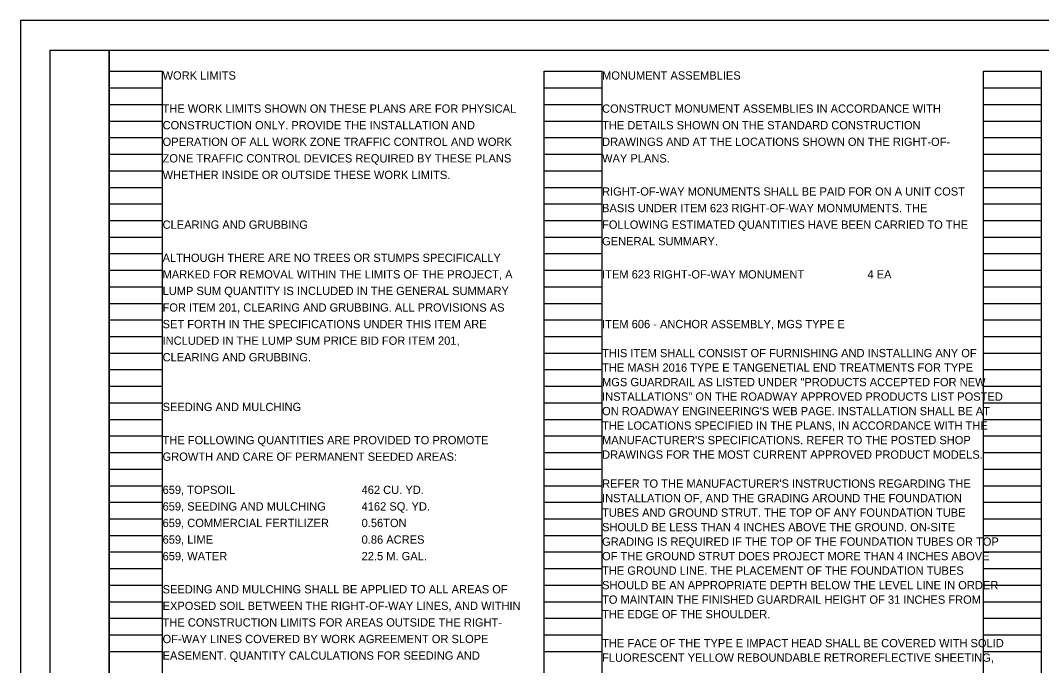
# Model space of a CAD drawing. Extents: x 0 to 34, y 0 to 22.
# Drawn here: x 0 to 17.24, y 11.1 to 22 of the extents above; entities that cross this region are included whole.
import ezdxf

# ---------------------------------------------------------------- set-up
doc = ezdxf.new("R2010")
doc.units = 0
for name, color, linetype in [('Default', 7, 'Continuous'), ('SH_Border', 7, 'Continuous'), ('SH_Cut_Line', 7, 'Continuous'), ('SH_Data', 7, 'Continuous'), ('SH_Text', 7, 'Continuous')]:
    doc.layers.add(name, color=color, linetype=linetype)

msp = doc.modelspace()

# ---------------------------------------------------------------- linework, layer by layer
at = {"layer": 'SH_Border'}
for points in [[(0.5, 21.5), (1.5, 21.5), (1.5, 0.5), (0.5, 0.5)], [(1.5, 21.5), (33.5, 21.5), (33.5, 0.5), (1.5, 0.5)]]:
    msp.add_lwpolyline(points, close=True, dxfattribs=at)
at = {"layer": 'SH_Cut_Line'}
msp.add_lwpolyline([(0, 0), (34, 0), (34, 22), (0, 22)], close=True, dxfattribs=at)
at = {"layer": 'SH_Data'}
for p, q in [((1.5, 0.98), (1.5, 21.14)), ((1.5, 21.14), (2.4, 21.14)), ((2.4, 0.98), (2.4, 21.14)), ((8.84, 0.98), (8.84, 21.14)), ((8.84, 21.14), (9.82, 21.14)), ((9.82, 0.98), (9.82, 21.14)), ((16.26, 0.98), (16.26, 21.14)), ((16.26, 21.14), (17.24, 21.14)), ((17.24, 0.98), (17.24, 21.14)), ((1.5, 20.86), (2.4, 20.86)), ((8.84, 20.86), (9.82, 20.86)), ((16.26, 20.86), (17.24, 20.86)), ((1.5, 20.58), (2.4, 20.58)), ((8.84, 20.58), (9.82, 20.58)), ((16.26, 20.58), (17.24, 20.58)), ((1.5, 20.3), (2.4, 20.3)), ((8.84, 20.3), (9.82, 20.3)), ((16.26, 20.3), (17.24, 20.3)), ((1.5, 20.02), (2.4, 20.02)), ((8.84, 20.02), (9.82, 20.02)), ((16.26, 20.02), (17.24, 20.02)), ((1.5, 19.74), (2.4, 19.74)), ((8.84, 19.74), (9.82, 19.74)), ((16.26, 19.74), (17.24, 19.74)), ((1.5, 19.46), (2.4, 19.46)), ((8.84, 19.46), (9.82, 19.46)), ((16.26, 19.46), (17.24, 19.46)), ((1.5, 19.18), (2.4, 19.18)), ((8.84, 19.18), (9.82, 19.18)), ((16.26, 19.18), (17.24, 19.18)), ((1.5, 18.9), (2.4, 18.9)), ((8.84, 18.9), (9.82, 18.9)), ((16.26, 18.9), (17.24, 18.9)), ((1.5, 18.62), (2.4, 18.62)), ((8.84, 18.62), (9.82, 18.62)), ((16.26, 18.62), (17.24, 18.62)), ((1.5, 18.34), (2.4, 18.34)), ((8.84, 18.34), (9.82, 18.34)), ((16.26, 18.34), (17.24, 18.34)), ((1.5, 18.06), (2.4, 18.06)), ((8.84, 18.06), (9.82, 18.06)), ((16.26, 18.06), (17.24, 18.06)), ((1.5, 17.78), (2.4, 17.78)), ((8.84, 17.78), (9.82, 17.78)), ((16.26, 17.78), (17.24, 17.78)), ((1.5, 17.5), (2.4, 17.5)), ((8.84, 17.5), (9.82, 17.5)), ((16.26, 17.5), (17.24, 17.5)), ((1.5, 17.22), (2.4, 17.22)), ((8.84, 17.22), (9.82, 17.22)), ((16.26, 17.22), (17.24, 17.22)), ((1.5, 16.94), (2.4, 16.94)), ((8.84, 16.94), (9.82, 16.94)), ((16.26, 16.94), (17.24, 16.94)), ((1.5, 16.66), (2.4, 16.66)), ((8.84, 16.66), (9.82, 16.66)), ((16.26, 16.66), (17.24, 16.66)), ((1.5, 16.38), (2.4, 16.38)), ((8.84, 16.38), (9.82, 16.38)), ((16.26, 16.38), (17.24, 16.38)), ((1.5, 16.1), (2.4, 16.1)), ((8.84, 16.1), (9.82, 16.1)), ((16.26, 16.1), (17.24, 16.1)), ((1.5, 15.82), (2.4, 15.82)), ((8.84, 15.82), (9.82, 15.82)), ((16.26, 15.82), (17.24, 15.82)), ((1.5, 15.54), (2.4, 15.54)), ((8.84, 15.54), (9.82, 15.54)), ((16.26, 15.54), (17.24, 15.54)), ((1.5, 15.26), (2.4, 15.26)), ((8.84, 15.26), (9.82, 15.26)), ((16.26, 15.26), (17.24, 15.26)), ((1.5, 14.98), (2.4, 14.98)), ((8.84, 14.98), (9.82, 14.98)), ((16.26, 14.98), (17.24, 14.98)), ((1.5, 14.7), (2.4, 14.7)), ((8.84, 14.7), (9.82, 14.7)), ((16.26, 14.7), (17.24, 14.7)), ((1.5, 14.42), (2.4, 14.42)), ((8.84, 14.42), (9.82, 14.42)), ((16.26, 14.42), (17.24, 14.42)), ((1.5, 14.14), (2.4, 14.14)), ((8.84, 14.14), (9.82, 14.14)), ((16.26, 14.14), (17.24, 14.14)), ((1.5, 13.86), (2.4, 13.86)), ((8.84, 13.86), (9.82, 13.86)), ((16.26, 13.86), (17.24, 13.86)), ((1.5, 13.58), (2.4, 13.58)), ((8.84, 13.58), (9.82, 13.58)), ((16.26, 13.58), (17.24, 13.58)), ((1.5, 13.3), (2.4, 13.3)), ((8.84, 13.3), (9.82, 13.3)), ((16.26, 13.3), (17.24, 13.3)), ((1.5, 13.02), (2.4, 13.02)), ((8.84, 13.02), (9.82, 13.02)), ((16.26, 13.02), (17.24, 13.02)), ((1.5, 12.74), (2.4, 12.74)), ((8.84, 12.74), (9.82, 12.74)), ((16.26, 12.74), (17.24, 12.74)), ((1.5, 12.46), (2.4, 12.46)), ((8.84, 12.46), (9.82, 12.46)), ((16.26, 12.46), (17.24, 12.46)), ((1.5, 12.18), (2.4, 12.18)), ((8.84, 12.18), (9.82, 12.18)), ((16.26, 12.18), (17.24, 12.18)), ((1.5, 11.9), (2.4, 11.9)), ((8.84, 11.9), (9.82, 11.9)), ((16.26, 11.9), (17.24, 11.9)), ((1.5, 11.62), (2.4, 11.62)), ((8.84, 11.62), (9.82, 11.62)), ((16.26, 11.62), (17.24, 11.62)), ((1.5, 11.34), (2.4, 11.34)), ((8.84, 11.34), (9.82, 11.34)), ((16.26, 11.34), (17.24, 11.34))]:
    msp.add_line(p, q, dxfattribs=at)

# ---------------------------------------------------------------- texts
at = {"layer": 'Default'}
for s, p in [('MONUMENT ASSEMBLIES', (9.82, 21)), ('CONSTRUCT MONUMENT ASSEMBLIES IN ACCORDANCE WITH', (9.82, 20.44)), ('THE DETAILS SHOWN ON THE STANDARD CONSTRUCTION', (9.82, 20.16)), ('DRAWINGS AND AT THE LOCATIONS SHOWN ON THE RIGHT-OF-', (9.82, 19.88)), ('WAY PLANS.', (9.82, 19.6)), ('RIGHT-OF-WAY MONUMENTS SHALL BE PAID FOR ON A UNIT COST ', (9.82, 19.04)), ('BASIS UNDER ITEM 623 RIGHT-OF-WAY MONMUMENTS. THE ', (9.82, 18.76)), ('FOLLOWING ESTIMATED QUANTITIES HAVE BEEN CARRIED TO THE ', (9.82, 18.48)), ('GENERAL SUMMARY.', (9.82, 18.2)), ('ITEM 623 RIGHT-OF-WAY MONUMENT', (9.82, 17.64)), ('4 EA', (14.3, 17.64))]:
    msp.add_text(s, height=0.14, dxfattribs=at).set_placement(p)
at = {"layer": 'SH_Text'}
for s, p in [('WORK LIMITS', (2.4, 21)), ('THE WORK LIMITS SHOWN ON THESE PLANS ARE FOR PHYSICAL', (2.4, 20.44)), ('CONSTRUCTION ONLY. PROVIDE THE INSTALLATION AND', (2.4, 20.16)), ('OPERATION OF ALL WORK ZONE TRAFFIC CONTROL AND WORK', (2.4, 19.88)), ('ZONE TRAFFIC CONTROL DEVICES REQUIRED BY THESE PLANS', (2.4, 19.6)), ('WHETHER INSIDE OR OUTSIDE THESE WORK LIMITS.', (2.4, 19.32)), ('CLEARING AND GRUBBING', (2.4, 18.48)), ('ALTHOUGH THERE ARE NO TREES OR STUMPS SPECIFICALLY', (2.4, 17.92)), ('MARKED FOR REMOVAL WITHIN THE LIMITS OF THE PROJECT, A', (2.4, 17.64)), ('LUMP SUM QUANTITY IS INCLUDED IN THE GENERAL SUMMARY', (2.4, 17.36)), ('FOR ITEM 201, CLEARING AND GRUBBING. ALL PROVISIONS AS', (2.4, 17.08)), ('SET FORTH IN THE SPECIFICATIONS UNDER THIS ITEM ARE', (2.4, 16.8)), ('ITEM 606 - ANCHOR ASSEMBLY, MGS TYPE E', (9.82, 16.8)), ('INCLUDED IN THE LUMP SUM PRICE BID FOR ITEM 201,', (2.4, 16.52)), ('CLEARING AND GRUBBING.', (2.4, 16.24)), ('THIS ITEM SHALL CONSIST OF FURNISHING AND INSTALLING ANY OF ', (9.82, 16.31)), ('THE MASH 2016 TYPE E TANGENETIAL END TREATMENTS FOR TYPE ', (9.82, 16.065)), ('MGS GUARDRAIL AS LISTED UNDER "PRODUCTS ACCEPTED FOR NEW ', (9.82, 15.82)), ('INSTALLATIONS" ON THE ROADWAY APPROVED PRODUCTS LIST POSTED ', (9.82, 15.575)), ('SEEDING AND MULCHING', (2.4, 15.4)), ("ON ROADWAY ENGINEERING'S WEB PAGE. INSTALLATION SHALL BE AT ", (9.82, 15.33)), ('THE LOCATIONS SPECIFIED IN THE PLANS, IN ACCORDANCE WITH THE ', (9.82, 15.085)), ('THE FOLLOWING QUANTITIES ARE PROVIDED TO PROMOTE', (2.4, 14.84)), ("MANUFACTURER'S SPECIFICATIONS. REFER TO THE POSTED SHOP ", (9.82, 14.84)), ('GROWTH AND CARE OF PERMANENT SEEDED AREAS:', (2.4, 14.56)), ('DRAWINGS FOR THE MOST CURRENT APPROVED PRODUCT MODELS.', (9.82, 14.595)), ('659, TOPSOIL', (2.4, 14)), ('462 CU. YD.', (5.76, 14)), ("REFER TO THE MANUFACTURER'S INSTRUCTIONS REGARDING THE ", (9.82, 14.105)), ('INSTALLATION OF, AND THE GRADING AROUND THE FOUNDATION ', (9.82, 13.86)), ('659, SEEDING AND MULCHING', (2.4, 13.72)), ('4162 SQ. YD.', (5.76, 13.72)), ('TUBES AND GROUND STRUT. THE TOP OF ANY FOUNDATION TUBE ', (9.82, 13.615)), ('659, COMMERCIAL FERTILIZER', (2.4, 13.44)), ('0.56TON', (5.76, 13.44)), ('SHOULD BE LESS THAN 4 INCHES ABOVE THE GROUND. ON-SITE ', (9.82, 13.37)), ('659, LIME', (2.4, 13.16)), ('0.86 ACRES', (5.76, 13.16)), ('GRADING IS REQUIRED IF THE TOP OF THE FOUNDATION TUBES OR TOP ', (9.82, 13.125)), ('659, WATER', (2.4, 12.88)), ('22.5 M. GAL.', (5.76, 12.88)), ('OF THE GROUND STRUT DOES PROJECT MORE THAN 4 INCHES ABOVE ', (9.82, 12.88)), ('THE GROUND LINE. THE PLACEMENT OF THE FOUNDATION TUBES ', (9.82, 12.635)), ('SEEDING AND MULCHING SHALL BE APPLIED TO ALL AREAS OF', (2.4, 12.32)), ('SHOULD BE AN APPROPRIATE DEPTH BELOW THE LEVEL LINE IN ORDER ', (9.82, 12.39)), ('TO MAINTAIN THE FINISHED GUARDRAIL HEIGHT OF 31 INCHES FROM ', (9.82, 12.145)), ('EXPOSED SOIL BETWEEN THE RIGHT-OF-WAY LINES, AND WITHIN', (2.4, 12.04)), ('THE CONSTRUCTION LIMITS FOR AREAS OUTSIDE THE RIGHT-', (2.4, 11.76)), ('THE EDGE OF THE SHOULDER.', (9.82, 11.9)), ('OF-WAY LINES COVERED BY WORK AGREEMENT OR SLOPE', (2.4, 11.48)), ('THE FACE OF THE TYPE E IMPACT HEAD SHALL BE COVERED WITH SOLID ', (9.82, 11.41)), ('EASEMENT. QUANTITY CALCULATIONS FOR SEEDING AND', (2.4, 11.2)), ('FLUORESCENT YELLOW REBOUNDABLE RETROREFLECTIVE SHEETING, ', (9.82, 11.165))]:
    msp.add_text(s, height=0.14, dxfattribs=at).set_placement(p)

doc.saveas('drawing.dxf')
